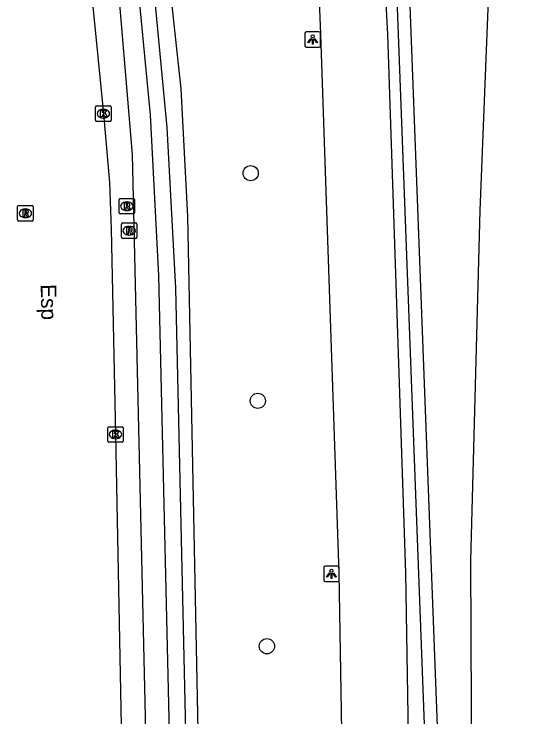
# Model space of a CAD drawing. Extents: x 161389 to 162585, y 388479 to 389761.
# Drawn here: x 162491.39 to 162525.4, y 389013.71 to 389058.96 of the extents above; entities that cross this region are included whole.
import ezdxf

# ---------------------------------------------------------------- set-up
doc = ezdxf.new("R2010")
doc.units = 0
for name, color, linetype in [('IMGEO_Berm_groen', 7, 'Continuous'), ('IMGEO_Boom', 7, 'Continuous'), ('IMGEO_Fietspad_gesloten', 7, 'Continuous'), ('IMGEO_Haag', 7, 'Continuous'), ('IMGEO_Kolk', 7, 'Continuous'), ('IMGEO_Lichtpunt', 7, 'Continuous'), ('IMGEO_Openbare_ruimte_label', 7, 'Continuous'), ('IMGEO_Rijbaan_lokaal_gesloten', 7, 'Continuous'), ('IMGEO_Rijbaan_regionaal_gesloten', 7, 'Continuous'), ('IMGEO_Rioolput', 7, 'Continuous'), ('IMGEO_Waterloop', 7, 'Continuous')]:
    doc.layers.add(name, color=color, linetype=linetype)

msp = doc.modelspace()

# ---------------------------------------------------------------- linework, layer by layer
at = {"layer": 'IMGEO_Berm_groen'}
for points in [[(162494.837, 389089.198), (162494.779, 389089.009), (162494.49, 389088.06), (162496.788, 389086.825), (162496.788, 389081.502), (162496.789, 389075.947), (162498.985, 389049.929), (162500, 389005.369), (162500.109, 389000), (162502.143, 388899.896)], [(162485.689, 388681.463), (162489.638, 388688.939), (162493.393, 388696.514), (162499.135, 388710.054), (162499.893, 388712.133), (162500, 388712.436), (162504.276, 388726.446), (162504.955, 388729.188), (162507.287, 388742.621), (162508.048, 388750), (162508.507, 388763.596), (162508.502, 388764.034), (162507.703, 388808.23), (162506.277, 388863.384), (162505.585, 388897.306), (162503.491, 389000), (162502.554, 389045.938), (162502.136, 389054.149), (162501.235, 389062.489), (162500.618, 389070.413), (162500.992, 389075.618), (162501.263, 389081.238), (162501.272, 389081.426)]]:
    msp.add_lwpolyline(points, dxfattribs=at)
at = {"layer": 'IMGEO_Boom'}
for centre in [(162506.603, 389048.718), (162507.06, 389034.063), (162507.648, 389018.266)]:
    msp.add_circle(centre, 0.489, dxfattribs=at)
at = {"layer": 'IMGEO_Fietspad_gesloten'}
for points in [[(162510.065, 389081.426), (162510.235, 389079.2), (162511.097, 389057.663), (162512.275, 389022.964), (162514.823, 388871.796), (162517.21, 388728.105)], [(162514.292, 389081.426), (162514.262, 389079.427), (162515.393, 389057.642), (162516.561, 389022.995), (162519.033, 388871.958), (162521.523, 388727.275)]]:
    msp.add_lwpolyline(points, dxfattribs=at)
at = {"layer": 'IMGEO_Haag'}
msp.add_lwpolyline([(162516.308, 389081.426), (162516.198, 389079.074), (162516.44, 389070.256), (162519.403, 388991.608), (162518.604, 388991.578), (162515.64, 389070.23)], dxfattribs=at)
at = {"layer": 'IMGEO_Kolk'}
for p, q in [((162496.629, 389052.123), (162496.629, 389052.975)), ((162496.704, 389053.049), (162497.556, 389053.049)), ((162497.117, 389052.829), (162497.142, 389052.829)), ((162497.63, 389052.975), (162497.63, 389052.123)), ((162497.14, 389052.269), (162497.115, 389052.269)), ((162497.556, 389052.049), (162496.704, 389052.049)), ((162497.483, 389032.401), (162498.335, 389032.401)), ((162497.408, 389031.475), (162497.408, 389032.327)), ((162497.896, 389032.181), (162497.921, 389032.181)), ((162498.409, 389032.327), (162498.409, 389031.475)), ((162497.919, 389031.621), (162497.894, 389031.621)), ((162498.335, 389031.401), (162497.483, 389031.401))]:
    msp.add_line(p, q, dxfattribs=at)
for points in [[(162496.629, 389052.123), (162496.629, 389052.975)], [(162496.704, 389053.049), (162497.556, 389053.049)], [(162496.95, 389052.749), (162497.073, 389052.749), (162497.073, 389052.598), (162497.203, 389052.749), (162497.367, 389052.749), (162497.221, 389052.598), (162497.374, 389052.349), (162497.222, 389052.349), (162497.137, 389052.513), (162497.073, 389052.446), (162497.073, 389052.349), (162496.95, 389052.349), (162496.95, 389052.749)], [(162497.63, 389052.975), (162497.63, 389052.123)], [(162497.556, 389052.049), (162496.704, 389052.049)], [(162497.483, 389032.401), (162498.335, 389032.401)], [(162497.408, 389031.475), (162497.408, 389032.327)], [(162497.729, 389032.101), (162497.852, 389032.101), (162497.852, 389031.95), (162497.982, 389032.101), (162498.146, 389032.101), (162498, 389031.95), (162498.153, 389031.701), (162498.001, 389031.701), (162497.916, 389031.865), (162497.852, 389031.798), (162497.852, 389031.701), (162497.729, 389031.701), (162497.729, 389032.101)], [(162498.409, 389032.327), (162498.409, 389031.475)], [(162498.335, 389031.401), (162497.483, 389031.401)]]:
    msp.add_lwpolyline(points, dxfattribs=at)
for centre, start, end in [((162496.706, 389052.973), 91.552, 178.448), ((162496.706, 389052.973), 91.552, 178.448), ((162497.554, 389052.973), 1.552, 88.448), ((162497.554, 389052.973), 1.552, 88.448), ((162496.706, 389052.125), 181.552, 268.448), ((162496.706, 389052.125), 181.552, 268.448), ((162497.554, 389052.125), 271.552, 358.448), ((162497.554, 389052.125), 271.552, 358.448), ((162497.485, 389032.325), 91.552, 178.448), ((162497.485, 389032.325), 91.552, 178.448), ((162498.333, 389032.325), 1.552, 88.448), ((162498.333, 389032.325), 1.552, 88.448), ((162497.485, 389031.477), 181.552, 268.448), ((162497.485, 389031.477), 181.552, 268.448), ((162498.333, 389031.477), 271.552, 358.448), ((162498.333, 389031.477), 271.552, 358.448)]:
    msp.add_arc(centre, 0.0765, start, end, dxfattribs=at)
for centre, major_axis, ratio, start_param, end_param in [((162497.116, 389052.549), (-0.387, 0.002), 0.722429, 4.712389, 7.853982), ((162497.141, 389052.549), (-0.39, 0.002), 0.717154, 1.570796, 4.712389), ((162497.895, 389031.901), (-0.387, 0.002), 0.722429, 4.712389, 7.853982), ((162497.92, 389031.901), (-0.39, 0.002), 0.717154, 1.570796, 4.712389)]:
    msp.add_ellipse(centre, major_axis=major_axis, ratio=ratio, start_param=start_param, end_param=end_param, dxfattribs=at)
at = {"layer": 'IMGEO_Lichtpunt'}
for p, q in [((162510.093, 389057.734), (162510.093, 389056.927)), ((162510.093, 389057.734), (162510.093, 389056.927)), ((162510.995, 389057.829), (162510.187, 389057.829)), ((162510.995, 389057.829), (162510.187, 389057.829)), ((162511.089, 389056.927), (162511.089, 389057.734)), ((162511.089, 389056.927), (162511.089, 389057.734)), ((162510.187, 389056.833), (162510.995, 389056.833)), ((162510.187, 389056.833), (162510.995, 389056.833)), ((162511.298, 389023.328), (162511.298, 389022.521)), ((162511.298, 389023.328), (162511.298, 389022.521)), ((162512.2, 389023.423), (162511.392, 389023.423)), ((162512.2, 389023.423), (162511.392, 389023.423)), ((162512.294, 389022.521), (162512.294, 389023.328)), ((162512.294, 389022.521), (162512.294, 389023.328)), ((162511.392, 389022.427), (162512.2, 389022.427)), ((162511.392, 389022.427), (162512.2, 389022.427))]:
    msp.add_line(p, q, dxfattribs=at)
for points in [[(162510.467, 389057.398), (162510.506, 389057.37), (162510.318, 389057.108), (162510.28, 389057.135), (162510.467, 389057.398)], [(162510.569, 389057.35), (162510.616, 389057.35), (162510.616, 389057.028), (162510.569, 389057.028), (162510.569, 389057.35)], [(162510.679, 389057.37), (162510.717, 389057.397), (162510.904, 389057.135), (162510.865, 389057.107), (162510.679, 389057.37)], [(162511.672, 389022.992), (162511.711, 389022.964), (162511.523, 389022.702), (162511.485, 389022.729), (162511.672, 389022.992)], [(162511.774, 389022.944), (162511.821, 389022.944), (162511.821, 389022.622), (162511.774, 389022.622), (162511.774, 389022.944)], [(162511.884, 389022.964), (162511.922, 389022.991), (162512.109, 389022.729), (162512.07, 389022.701), (162511.884, 389022.964)]]:
    msp.add_lwpolyline(points, dxfattribs=at)
for centre in [(162510.592, 389057.532), (162511.797, 389023.126)]:
    msp.add_circle(centre, 0.0994, dxfattribs=at)
for centre, start, end in [((162510.187, 389057.734), 90, 180), ((162510.187, 389057.734), 90, 180), ((162510.995, 389057.734), 0, 90), ((162510.995, 389057.734), 0, 90), ((162510.187, 389056.927), 180, 270), ((162510.187, 389056.927), 180, 270), ((162510.995, 389056.927), 270, 0), ((162510.995, 389056.927), 270, 360), ((162511.392, 389023.328), 90, 180), ((162511.392, 389023.328), 90, 180), ((162512.2, 389023.328), 0, 90), ((162512.2, 389023.328), 0, 90), ((162511.392, 389022.521), 180, 270), ((162511.392, 389022.521), 180, 270), ((162512.2, 389022.521), 270, 0), ((162512.2, 389022.521), 270, 360)]:
    msp.add_arc(centre, 0.0946, start, end, dxfattribs=at)
at = {"layer": 'IMGEO_Rijbaan_lokaal_gesloten'}
msp.add_lwpolyline([(162490.342, 389085.308), (162490.787, 389084.821), (162491.693, 389083.633), (162492.051, 389083.076), (162492.454, 389082.404), (162493.247, 389080.862), (162493.9, 389079.256), (162494.406, 389077.597), (162494.762, 389075.9), (162495.027, 389073.715), (162497.129, 389052.548), (162497.513, 389048.118), (162497.623, 389045.106), (162497.908, 389031.901), (162498.323, 389010.953), (162498.544, 389000), (162498.738, 388990.354), (162499.125, 388969.925), (162499.542, 388948.383), (162499.929, 388927.993), (162500, 388924.891), (162500.417, 388906.674), (162500.546, 388899.883)], dxfattribs=at)
at = {"layer": 'IMGEO_Rijbaan_regionaal_gesloten'}
msp.add_lwpolyline([(162523.006, 389081.426), (162522.22, 389068.571), (162521.349, 389046.314), (162520.739, 389023.777), (162520.838, 389000), (162520.774, 388990.381), (162522.364, 388884.975), (162523.635, 388828.454), (162524.277, 388798.785), (162524.652, 388775.367), (162524.813, 388770.581), (162525.392, 388750.463), (162525.398, 388750), (162525.385, 388736.547)], dxfattribs=at)
at = {"layer": 'IMGEO_Rioolput'}
for p, q in [((162498.139, 389046.167), (162498.139, 389047.019)), ((162498.214, 389047.093), (162499.066, 389047.093)), ((162498.627, 389046.873), (162498.652, 389046.873)), ((162499.14, 389047.019), (162499.14, 389046.167)), ((162491.615, 389045.714), (162491.615, 389046.566)), ((162491.69, 389046.64), (162492.542, 389046.64)), ((162492.103, 389046.42), (162492.128, 389046.42)), ((162492.616, 389046.566), (162492.616, 389045.714)), ((162499.066, 389046.093), (162498.214, 389046.093)), ((162498.65, 389046.313), (162498.625, 389046.313)), ((162492.542, 389045.64), (162491.69, 389045.64)), ((162492.126, 389045.86), (162492.101, 389045.86)), ((162498.361, 389045.516), (162499.213, 389045.516)), ((162498.286, 389044.59), (162498.286, 389045.442)), ((162498.774, 389045.296), (162498.799, 389045.296)), ((162499.287, 389045.442), (162499.287, 389044.59)), ((162498.797, 389044.736), (162498.772, 389044.736)), ((162499.213, 389044.516), (162498.361, 389044.516))]:
    msp.add_line(p, q, dxfattribs=at)
for points in [[(162498.139, 389046.167), (162498.139, 389047.019)], [(162498.214, 389047.093), (162499.066, 389047.093)], [(162499.14, 389047.019), (162499.14, 389046.167)], [(162491.615, 389045.714), (162491.615, 389046.566)], [(162491.69, 389046.64), (162492.542, 389046.64)], [(162492.616, 389046.566), (162492.616, 389045.714)], [(162498.728, 389046.791), (162498.476, 389046.793), (162498.476, 389046.393)], [(162498.476, 389046.393), (162498.6, 389046.393), (162498.6, 389046.555), (162498.611, 389046.555)], [(162498.654, 389046.712), (162498.6, 389046.712), (162498.6, 389046.631)], [(162498.6, 389046.631), (162498.652, 389046.631)], [(162498.658, 389046.526), (162498.729, 389046.393), (162498.869, 389046.393), (162498.804, 389046.519)], [(162492.204, 389046.338), (162491.952, 389046.34), (162491.952, 389045.94)], [(162491.952, 389045.94), (162492.076, 389045.94), (162492.076, 389046.102), (162492.087, 389046.102)], [(162492.13, 389046.259), (162492.076, 389046.259), (162492.076, 389046.178)], [(162492.076, 389046.178), (162492.128, 389046.178)], [(162492.134, 389046.073), (162492.205, 389045.94), (162492.345, 389045.94), (162492.28, 389046.066)], [(162499.066, 389046.093), (162498.214, 389046.093)], [(162492.542, 389045.64), (162491.69, 389045.64)], [(162498.361, 389045.516), (162499.213, 389045.516)], [(162498.286, 389044.59), (162498.286, 389045.442)], [(162498.875, 389045.214), (162498.623, 389045.216), (162498.623, 389044.816)], [(162498.801, 389045.135), (162498.747, 389045.135), (162498.747, 389045.054)], [(162498.747, 389045.054), (162498.799, 389045.054)], [(162499.287, 389045.442), (162499.287, 389044.59)], [(162498.623, 389044.816), (162498.747, 389044.816), (162498.747, 389044.978), (162498.758, 389044.978)], [(162498.805, 389044.949), (162498.876, 389044.816), (162499.016, 389044.816), (162498.951, 389044.942)], [(162499.213, 389044.516), (162498.361, 389044.516)]]:
    msp.add_lwpolyline(points, dxfattribs=at)
for centre, radius, start, end in [((162498.216, 389047.017), 0.0765, 91.552, 178.448), ((162498.216, 389047.017), 0.0765, 91.552, 178.448), ((162499.064, 389047.017), 0.0765, 1.552, 88.448), ((162499.064, 389047.017), 0.0765, 1.552, 88.448), ((162491.692, 389046.564), 0.0765, 91.552, 178.448), ((162491.692, 389046.564), 0.0765, 91.552, 178.448), ((162492.54, 389046.564), 0.0765, 1.552, 88.448), ((162492.54, 389046.564), 0.0765, 1.552, 88.448), ((162498.61, 389046.502), 0.0533, 26.0293, 88.6989), ((162498.636, 389046.82), 0.19, 274.7715, 282.9687), ((162498.66, 389046.616), 0.0964, 77.0061, 93.1865), ((162498.674, 389046.673), 0.0378, 276.6634, 79.6772), ((162498.727, 389046.681), 0.109, 350.3612, 89.416), ((162498.725, 389046.681), 0.112, 277.5842, 350.9817), ((162498.709, 389046.466), 0.108, 29.5134, 73.7905), ((162492.086, 389046.049), 0.0533, 26.0293, 88.6989), ((162492.112, 389046.367), 0.19, 274.7715, 282.9687), ((162492.136, 389046.163), 0.0964, 77.0061, 93.1865), ((162492.15, 389046.22), 0.0378, 276.6634, 79.6772), ((162492.203, 389046.228), 0.109, 350.3612, 89.416), ((162492.201, 389046.228), 0.112, 277.5842, 350.9817), ((162492.185, 389046.013), 0.108, 29.5134, 73.7905), ((162498.216, 389046.169), 0.0765, 181.552, 268.448), ((162498.216, 389046.169), 0.0765, 181.552, 268.448), ((162499.064, 389046.169), 0.0765, 271.552, 358.448), ((162499.064, 389046.169), 0.0765, 271.552, 358.448), ((162491.692, 389045.716), 0.0765, 181.552, 268.448), ((162491.692, 389045.716), 0.0765, 181.552, 268.448), ((162492.54, 389045.716), 0.0765, 271.552, 358.448), ((162492.54, 389045.716), 0.0765, 271.552, 358.448), ((162498.363, 389045.44), 0.0765, 91.552, 178.448), ((162498.363, 389045.44), 0.0765, 91.552, 178.448), ((162499.211, 389045.44), 0.0765, 1.552, 88.448), ((162499.211, 389045.44), 0.0765, 1.552, 88.448), ((162498.783, 389045.243), 0.19, 274.7715, 282.9687), ((162498.807, 389045.039), 0.0964, 77.0061, 93.1865), ((162498.821, 389045.096), 0.0378, 276.6634, 79.6772), ((162498.874, 389045.104), 0.109, 350.3612, 89.416), ((162498.872, 389045.104), 0.112, 277.5842, 350.9817), ((162498.363, 389044.592), 0.0765, 181.552, 268.448), ((162498.363, 389044.592), 0.0765, 181.552, 268.448), ((162498.757, 389044.925), 0.0533, 26.0293, 88.6989), ((162498.856, 389044.889), 0.108, 29.5134, 73.7905), ((162499.211, 389044.592), 0.0765, 271.552, 358.448), ((162499.211, 389044.592), 0.0765, 271.552, 358.448)]:
    msp.add_arc(centre, radius, start, end, dxfattribs=at)
for centre, major_axis, ratio, start_param, end_param in [((162498.626, 389046.593), (-0.387, 0.002), 0.722429, 4.712389, 7.853982), ((162498.651, 389046.593), (-0.39, 0.002), 0.717154, 1.570796, 4.712389), ((162492.102, 389046.14), (-0.387, 0.002), 0.722429, 4.712389, 7.853982), ((162492.127, 389046.14), (-0.39, 0.002), 0.717154, 1.570796, 4.712389), ((162498.773, 389045.016), (-0.387, 0.002), 0.722429, 4.712389, 7.853982), ((162498.798, 389045.016), (-0.39, 0.002), 0.717154, 1.570796, 4.712389)]:
    msp.add_ellipse(centre, major_axis=major_axis, ratio=ratio, start_param=start_param, end_param=end_param, dxfattribs=at)
at = {"layer": 'IMGEO_Waterloop'}
for points in [[(162504.505, 388860.971), (162503.038, 388926.396), (162502.659, 388946.624), (162502.127, 388965.964), (162501.881, 388981.345), (162501.365, 389013.623), (162500.705, 389042.133), (162500.155, 389052.486), (162498.345, 389071.465), (162498.581, 389076.587), (162498.739, 389086.449), (162498.772, 389086.623), (162498.826, 389086.782), (162498.892, 389086.879), (162499.066, 389086.995)], [(162499.712, 389086.909), (162499.807, 389086.78), (162499.841, 389086.613), (162499.834, 389086.44), (162499.637, 389075.77), (162499.401, 389070.648), (162501.211, 389051.669), (162501.761, 389041.317), (162502.421, 389012.807), (162502.937, 388980.529), (162503.183, 388965.148), (162503.715, 388945.808), (162504.093, 388925.58), (162505.561, 388860.155)]]:
    msp.add_lwpolyline(points, dxfattribs=at)

# ---------------------------------------------------------------- texts
at = {"layer": 'IMGEO_Openbare_ruimte_label'}
msp.add_text('Esp', height=1, rotation=271.1458, dxfattribs=at).set_placement((162493.097, 389041.564))

doc.saveas('drawing.dxf')
